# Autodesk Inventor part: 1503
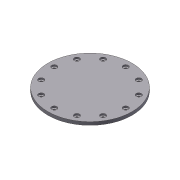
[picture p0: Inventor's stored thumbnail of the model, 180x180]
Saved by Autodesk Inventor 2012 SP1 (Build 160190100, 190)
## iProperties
Created: 2012-02
Part Number: 1503
Material: Aluminum-6061
Document SubType Name: Modeling
Designer: LACO
Density: 2.71 g/cm^3
Mass: 1274.08 g
Surface Area: 1110.77 cm^2
Volume: 470.139 cm^3
Author: LACO
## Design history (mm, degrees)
sketch "Sketch1"
  geometry: C1 r 127 at (0, 0); 1 further point
  constraints: 1 centre point, 1 coincident
  dimensions: "d1" = 254 diameter of C1
extrude "Extrusion1" new body sketch "Sketch1" distance "d2" = 9.525; taper "d3" = 0 deg
sketch "Sketch3"
  geometry: C1 r 127 at (0, 0) reference; C2 r 81.153 at (0, 0); C3 r 127 at (0, 0) reference
  constraints: 1 centre point, 1 coincident
  dimensions: "d18" = 162.306 diameter of C2
extrude "Extrusion2" join sketch "Sketch3" distance "d19" = 2.032; taper "d20" = 0 deg
sketch "Sketch2"
  geometry: L1 (0, 0)-(107.95, 0); C1 r 127 at (0, 0) reference; 1 further point
  constraints: 2 end point, 1 coincident, 1 horizontal
  dimensions: "d4" = 107.95 distance of L1.start L1.end
hole "Hole1" sketch "Sketch2" at (107.95, 0) diameter "d5" = 6.7564; stored, may be unused: countersink angle "d9" = 82 deg, drill point angle "d11" = 118 deg; dims "d6" = 19.05, "d7" = 15.875, "d8" = 4.826, "d10" = 25.4
pattern_circular "Circular Pattern1" dims angle "d13" = 360 deg
sketch "Sketch4"
  geometry: L1 (0, 0)-(69.85, 0); L2 (0, 0)-(-34.925, 60.492); L3 (0, 0)-(-34.925, -60.492); C1 r 81.153 at (0, 0) reference; A1 r 69.85 centre (0, 0) between (69.85, 0) and (-34.925, -60.492); 2 further points
  constraints: 6 end point, 4 coincident, 3 point on circle, 1 centre point, 1 horizontal
  dimensions: "d36" = 139.7 diameter of A1; "d37" = 120 deg angle of L1 L2; "d38" = 120 deg angle of L1 L3
hole "Hole2" sketch "Sketch4" at (69.85, 0), (-34.925, 60.492), (-34.925, -60.492) diameter "d22" = 4.9784; stored, may be unused: countersink angle "d26" = 82 deg, drill point angle "d28" = 118 deg; dims "d23" = 5.08, "d24" = 3.0226, "d25" = 4.7752, "d27" = 7.62
sketch "Sketch5"
  geometry: C1 r 81.153 at (0, 0) reference; C2 r 53.848 at (0, 0); C3 r 50.8 at (0, 0)
  constraints: 2 centre point, 2 coincident
  dimensions: "d32" = 3.048 radial gap between concentric circles of C2 C3; "d33" = 101.6 diameter of C3
extrude "Extrusion3" join sketch "Sketch5" distance "d34" = 2.032; taper "d35" = 0 deg
sketch "Sketch6"
  geometry: L1 (0, 120.65)-(0, -120.65); L2 (0.635, -95.949)-(2.007, -95.949); L3 (2.642, -95.314)-(2.642, -91.961); L4 (2.007, -91.326)-(0.635, -91.326); L5 (0, -96.584)-(0, -90.691); L6 (0, -93.637)-(2.642, -93.637); L7 (0, 127)-(0, -127) reference; L8 (-0.712, 0)-(3.354, 0) reference; A1 r 0.635 centre (0.635, -96.584) between (0.635, -95.949) and (0, -96.584); A2 r 0.635 centre (0.635, -90.691) between (0, -90.691) and (0.635, -91.326); A3 r 0.635 centre (2.007, -91.961) between (2.642, -91.961) and (2.007, -91.326); A4 r 0.635 centre (2.007, -95.314) between (2.007, -95.949) and (2.642, -95.314); 1 further point
  constraints: 12 end point, 8 point on circle, 8 tangent, 4 centre point, 3 equal radius, 3 midpoint, 3 perpendicular, 2 collinear, 1 parallel, 1 point on line
  dimensions: "d39" = 0.635 radius of A1; "d40" = 2.6416 distance between parallel lines of L3 L1; "d41" = 4.6228 distance between parallel lines of L4 L2; "d42" = 93.6371 distance from line of point (0, 0) L6
revolve "Revolution2" sketch "Sketch6" stored, may be unused: angle "d44" = 90 deg
node "Projected Loop1"
body "Solid2"
